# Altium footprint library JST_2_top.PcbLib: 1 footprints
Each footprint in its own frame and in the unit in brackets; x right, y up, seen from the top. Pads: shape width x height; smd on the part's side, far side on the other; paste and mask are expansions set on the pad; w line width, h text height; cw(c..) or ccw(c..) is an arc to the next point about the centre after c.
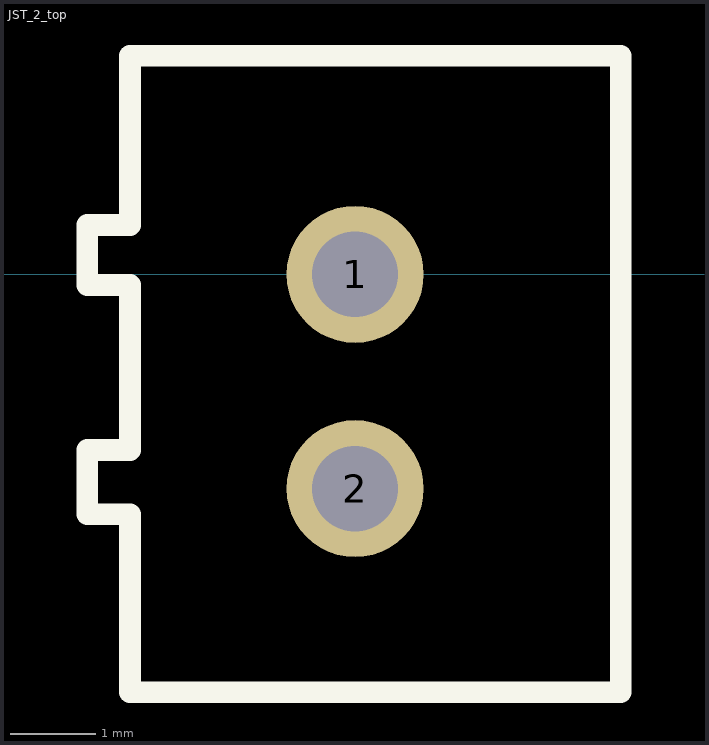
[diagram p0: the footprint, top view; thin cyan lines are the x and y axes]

## JST_2_top [mm]
pads (2):
  round 1.6 hole 1: 1(-5,0) 2(-5,-2.5)
Top Overlay:
  lines w0.254: -8.125,-2.8 -7.625,-2.8 -7.625,-4.875 -1.9,-4.875 -1.9,2.55 -7.625,2.55 -7.625,0.575 -8.125,0.575 -8.125,-0.125 -7.625,-0.125 -7.625,-2.05 -8.125,-2.05 -8.125,-2.8
3D body: height 7, standoff 0, extent -8.252,-5.002 -1.773,2.677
